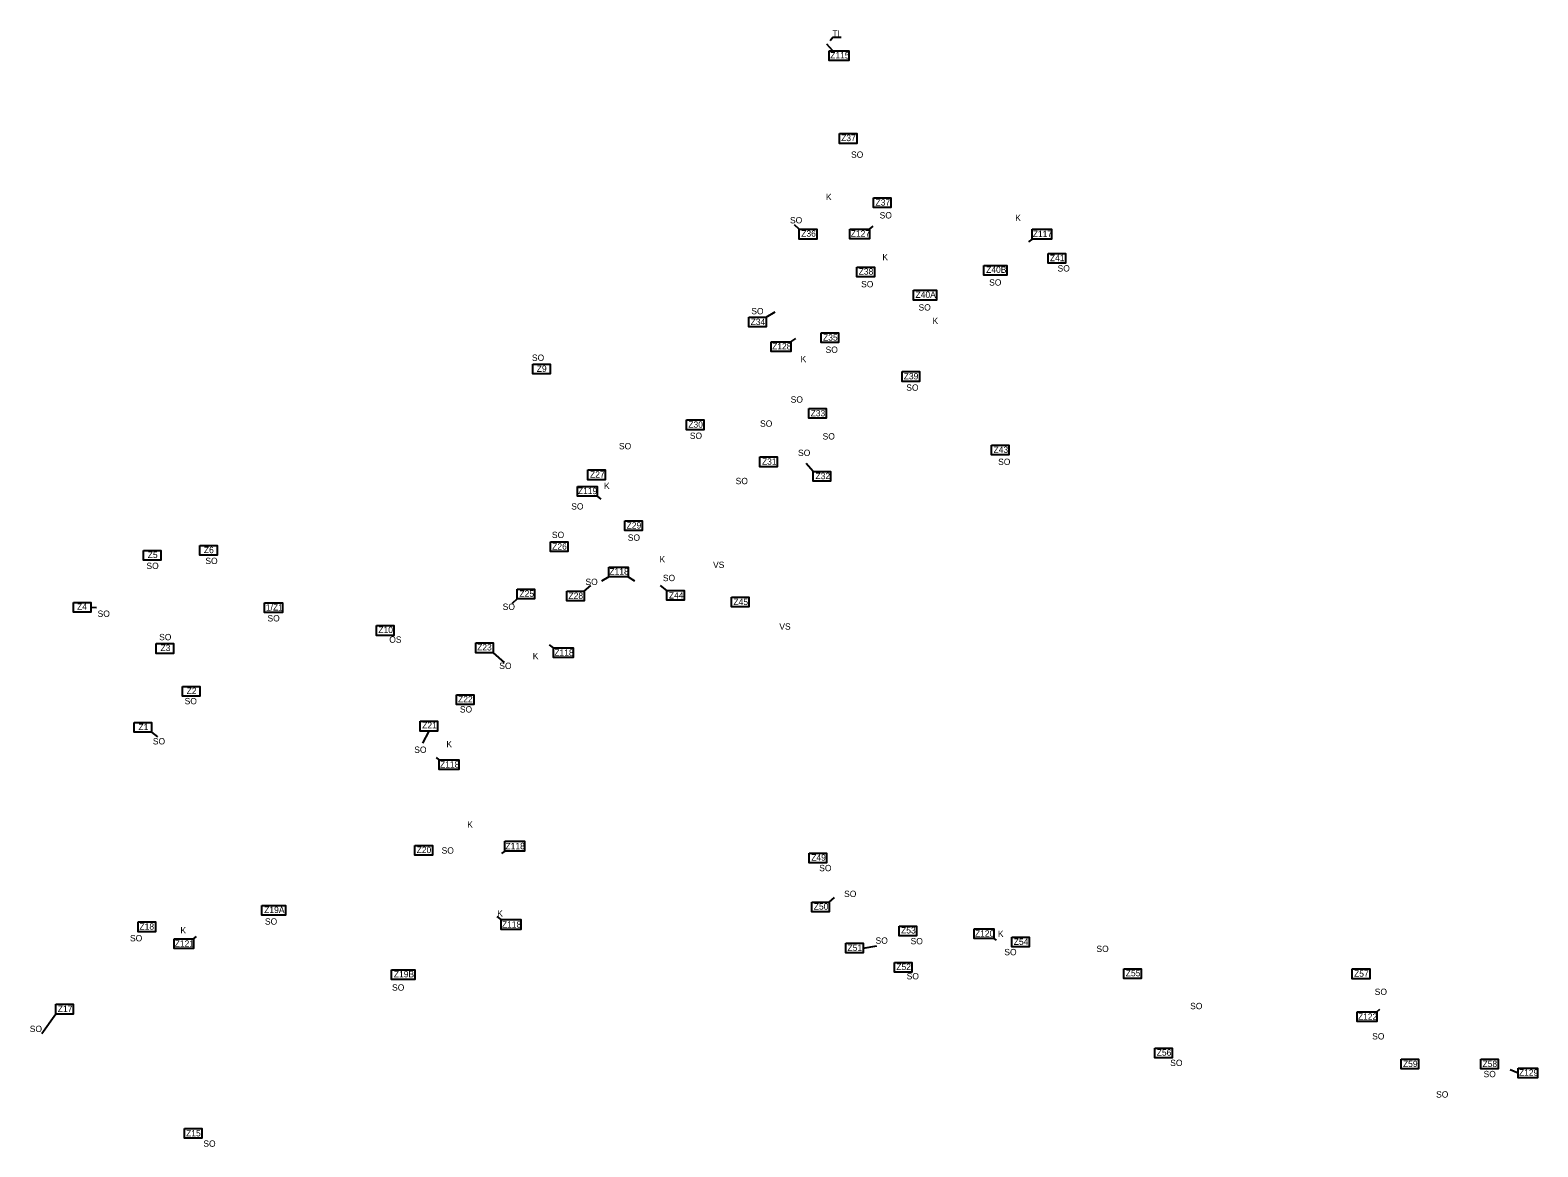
# Model space of a CAD drawing. Extents: x -443519 to -431242, y -1133468 to -1129615.
# Drawn here: x -443043 to -440666, y -1131535 to -1129775 of the extents above; entities that cross this region are included whole.
import ezdxf

# ---------------------------------------------------------------- set-up
doc = ezdxf.new("R2010")
doc.units = 0
for name, color, linetype in [('Vrstva 3', 7, 'Continuous'), ('Vrstva 4', 7, 'Continuous'), ('Vrstva 8', 7, 'Continuous')]:
    doc.layers.add(name, color=color, linetype=linetype)

msp = doc.modelspace()

# ---------------------------------------------------------------- linework, layer by layer
at = {"layer": 'Vrstva 3'}
for p, q in [((-441777.7, -1129807.7), (-441786.9, -1129797.4)), ((-441830.5, -1130088.9), (-441838, -1130081.7)), ((-441808.5, -1130470.4), (-441819.7, -1130457.7)), ((-442169.8, -1130659.1), (-442159.4, -1130650.4)), ((-442039.5, -1130658.1), (-442049.1, -1130650.3)), ((-442275.3, -1130671.3), (-442283.1, -1130678.3)), ((-442947.3, -1130684.5), (-442938.5, -1130684.6)), ((-442313.2, -1130756), (-442295.7, -1130771.4)), ((-442851.5, -1130881.4), (-442842.3, -1130888.4)), ((-442414.7, -1130879.5), (-442424.6, -1130898.5)), ((-441783.2, -1131148.9), (-441775.1, -1131141.9)), ((-441729.8, -1131221.4), (-441708.1, -1131217.9)), ((-443002.5, -1131325.5), (-443024.8, -1131356.8))]:
    msp.add_line(p, q, dxfattribs=at)
for points in [[(-441783.2, -1129807.7), (-441752.4, -1129807.7), (-441752.4, -1129823.1), (-441783.2, -1129823.1)], [(-441767.1, -1129938.1), (-441739.7, -1129938.1), (-441739.7, -1129953.5), (-441767.1, -1129953.5)], [(-441713.5, -1130039.3), (-441686.2, -1130039.3), (-441686.2, -1130054.7), (-441713.5, -1130054.7)], [(-441830.5, -1130088.9), (-441803.1, -1130088.9), (-441803.1, -1130104.3), (-441830.5, -1130104.3)], [(-441438.1, -1130126.8), (-441410.7, -1130126.8), (-441410.7, -1130142.2), (-441438.1, -1130142.2)], [(-441739.6, -1130148.5), (-441712.2, -1130148.5), (-441712.2, -1130163.9), (-441739.6, -1130163.9)], [(-441539.4, -1130145.7), (-441503.3, -1130145.7), (-441503.3, -1130161.1), (-441539.4, -1130161.1)], [(-441650.7, -1130185), (-441614.1, -1130185), (-441614.1, -1130200.4), (-441650.7, -1130200.4)], [(-441909.9, -1130227.3), (-441882.6, -1130227.3), (-441882.6, -1130242.7), (-441909.9, -1130242.7)], [(-441796.3, -1130252.1), (-441768.9, -1130252.1), (-441768.9, -1130267.5), (-441796.3, -1130267.5)], [(-442250.7, -1130301.4), (-442223.3, -1130301.4), (-442223.3, -1130316.8), (-442250.7, -1130316.8)], [(-441668.4, -1130313.2), (-441641, -1130313.2), (-441641, -1130328.6), (-441668.4, -1130328.6)], [(-441815.5, -1130371.3), (-441788.2, -1130371.3), (-441788.2, -1130386.7), (-441815.5, -1130386.7)], [(-442008.5, -1130389.3), (-441981.2, -1130389.3), (-441981.2, -1130404.7), (-442008.5, -1130404.7)], [(-441527.5, -1130428.9), (-441500.2, -1130428.9), (-441500.2, -1130444.3), (-441527.5, -1130444.3)], [(-441893, -1130447.6), (-441865.6, -1130447.6), (-441865.6, -1130463), (-441893, -1130463)], [(-442163.9, -1130468.1), (-442136.5, -1130468.1), (-442136.5, -1130483.5), (-442163.9, -1130483.5)], [(-441808.5, -1130470.4), (-441781.1, -1130470.4), (-441781.1, -1130485.8), (-441808.5, -1130485.8)], [(-442105.4, -1130548.2), (-442078, -1130548.2), (-442078, -1130563.6), (-442105.4, -1130563.6)], [(-442222.8, -1130581.2), (-442195.5, -1130581.2), (-442195.5, -1130596.5), (-442222.8, -1130596.5)], [(-442864.1, -1130595.1), (-442836.8, -1130595.1), (-442836.8, -1130610.4), (-442864.1, -1130610.4)], [(-442775.7, -1130587.1), (-442748.3, -1130587.1), (-442748.3, -1130602.5), (-442775.7, -1130602.5)], [(-442275.3, -1130655.9), (-442247.9, -1130655.9), (-442247.9, -1130671.3), (-442275.3, -1130671.3)], [(-442039.5, -1130658.1), (-442012.1, -1130658.1), (-442012.1, -1130673.5), (-442039.5, -1130673.5)], [(-442974.7, -1130676.8), (-442947.3, -1130676.8), (-442947.3, -1130692.2), (-442974.7, -1130692.2)], [(-442673.7, -1130677.5), (-442645, -1130677.5), (-442645, -1130692.9), (-442673.7, -1130692.9)], [(-442197.1, -1130659.1), (-442169.8, -1130659.1), (-442169.8, -1130674.5), (-442197.1, -1130674.5)], [(-441937.3, -1130668.5), (-441909.9, -1130668.5), (-441909.9, -1130683.9), (-441937.3, -1130683.9)], [(-442497.1, -1130713.3), (-442469.7, -1130713.3), (-442469.7, -1130728.7), (-442497.1, -1130728.7)], [(-442844.2, -1130741.8), (-442816.9, -1130741.8), (-442816.9, -1130757.2), (-442844.2, -1130757.2)], [(-442340.6, -1130740.6), (-442313.2, -1130740.6), (-442313.2, -1130756), (-442340.6, -1130756)], [(-442802.8, -1130809.3), (-442775.4, -1130809.3), (-442775.4, -1130824.7), (-442802.8, -1130824.7)], [(-442370.9, -1130822.5), (-442343.6, -1130822.5), (-442343.6, -1130837.9), (-442370.9, -1130837.9)], [(-442878.9, -1130866.1), (-442851.5, -1130866.1), (-442851.5, -1130881.4), (-442878.9, -1130881.4)], [(-442428.4, -1130864.1), (-442401, -1130864.1), (-442401, -1130879.5), (-442428.4, -1130879.5)], [(-442436.4, -1131059.8), (-442409, -1131059.8), (-442409, -1131075.2), (-442436.4, -1131075.2)], [(-441815, -1131072), (-441787.6, -1131072), (-441787.6, -1131087.4), (-441815, -1131087.4)], [(-442677.7, -1131154.3), (-442640.5, -1131154.3), (-442640.5, -1131169.7), (-442677.7, -1131169.7)], [(-441810.6, -1131148.9), (-441783.2, -1131148.9), (-441783.2, -1131164.3), (-441810.6, -1131164.3)], [(-442872.7, -1131180.4), (-442845.3, -1131180.4), (-442845.3, -1131195.7), (-442872.7, -1131195.7)], [(-441673.2, -1131186.9), (-441645.8, -1131186.9), (-441645.8, -1131202.2), (-441673.2, -1131202.2)], [(-441495.6, -1131204.2), (-441468.2, -1131204.2), (-441468.2, -1131219.6), (-441495.6, -1131219.6)], [(-441757.2, -1131213.7), (-441729.8, -1131213.7), (-441729.8, -1131229.1), (-441757.2, -1131229.1)], [(-441680.5, -1131244), (-441653.2, -1131244), (-441653.2, -1131259.4), (-441680.5, -1131259.4)], [(-442473.2, -1131255.7), (-442436.5, -1131255.7), (-442436.5, -1131271.1), (-442473.2, -1131271.1)], [(-441319, -1131254), (-441291.6, -1131254), (-441291.6, -1131269.4), (-441319, -1131269.4)], [(-440958.8, -1131254.3), (-440931.4, -1131254.3), (-440931.4, -1131269.7), (-440958.8, -1131269.7)], [(-443002.5, -1131310.1), (-442975.2, -1131310.1), (-442975.2, -1131325.5), (-443002.5, -1131325.5)], [(-441270.2, -1131379), (-441242.8, -1131379), (-441242.8, -1131394.4), (-441270.2, -1131394.4)], [(-440882, -1131396.5), (-440854.6, -1131396.5), (-440854.6, -1131411.9), (-440882, -1131411.9)], [(-440756.3, -1131396.5), (-440728.9, -1131396.5), (-440728.9, -1131411.9), (-440756.3, -1131411.9)], [(-442799.7, -1131505.6), (-442772.3, -1131505.6), (-442772.3, -1131521), (-442799.7, -1131521)]]:
    msp.add_lwpolyline(points, close=True, dxfattribs=at)
at = {"layer": 'Vrstva 4'}
msp.add_lwpolyline([(-441764.3, -1129786.7), (-441777.7, -1129786.7), (-441781.9, -1129791.9)], dxfattribs=at)
at = {"layer": 'Vrstva 8'}
for p, q in [((-441720.1, -1130088.6), (-441714.3, -1130084)), ((-441463.6, -1130104.2), (-441469.4, -1130108.5)), ((-441882.6, -1130227.3), (-441868.4, -1130219.1)), ((-441844, -1130266.2), (-441836.1, -1130260.9)), ((-442149.3, -1130509.6), (-442143.6, -1130514.2)), ((-442131, -1130636.5), (-442142.2, -1130643.1)), ((-442100.3, -1130636.5), (-442090.5, -1130642.7)), ((-442217.8, -1130748.4), (-442224.2, -1130743.6)), ((-442398, -1130924.7), (-442402.3, -1130921.1)), ((-442294.8, -1131068.6), (-442299.8, -1131072.4)), ((-442300.3, -1131176.7), (-442306.7, -1131171.9)), ((-442785.3, -1131206.9), (-442780.8, -1131203.4)), ((-441523.9, -1131206.4), (-441520.2, -1131209.2)), ((-440920.2, -1131322), (-440915.5, -1131317.9)), ((-440697.5, -1131418.4), (-440709.9, -1131413.3))]:
    msp.add_line(p, q, dxfattribs=at)
for points in [[(-441750.9, -1130088.6), (-441720.1, -1130088.6), (-441720.1, -1130104), (-441750.9, -1130104)], [(-441463.6, -1130088.8), (-441432.8, -1130088.8), (-441432.8, -1130104.2), (-441463.6, -1130104.2)], [(-441463.6, -1130088.8), (-441432.8, -1130088.8), (-441432.8, -1130104.2), (-441463.6, -1130104.2)], [(-441874.8, -1130266.2), (-441844, -1130266.2), (-441844, -1130281.6), (-441874.8, -1130281.6)], [(-442180.1, -1130494.2), (-442149.3, -1130494.2), (-442149.3, -1130509.6), (-442180.1, -1130509.6)], [(-442131, -1130621.1), (-442100.3, -1130621.1), (-442100.3, -1130636.5), (-442131, -1130636.5)], [(-442217.8, -1130748.4), (-442187, -1130748.4), (-442187, -1130763.8), (-442217.8, -1130763.8)], [(-442398, -1130924.7), (-442367.2, -1130924.7), (-442367.2, -1130940.1), (-442398, -1130940.1)], [(-442294.8, -1131053.2), (-442264, -1131053.2), (-442264, -1131068.6), (-442294.8, -1131068.6)], [(-442300.3, -1131176.7), (-442269.5, -1131176.7), (-442269.5, -1131192.1), (-442300.3, -1131192.1)], [(-441554.7, -1131191), (-441523.9, -1131191), (-441523.9, -1131206.4), (-441554.7, -1131206.4)], [(-442816.1, -1131206.9), (-442785.3, -1131206.9), (-442785.3, -1131222.3), (-442816.1, -1131222.3)], [(-440951, -1131322), (-440920.2, -1131322), (-440920.2, -1131337.4), (-440951, -1131337.4)], [(-440697.5, -1131410.7), (-440666.8, -1131410.7), (-440666.8, -1131426.1), (-440697.5, -1131426.1)]]:
    msp.add_lwpolyline(points, close=True, dxfattribs=at)

# ---------------------------------------------------------------- texts
at = {"layer": 'Vrstva 3'}
for s, p in [('Z115', (-441781.8, -1129819.7)), ('Z37', (-441764.6, -1129949.9)), ('Z37', (-441710.4, -1130051.5)), ('Z36', (-441827.5, -1130100.6)), ('Z41', (-441435.5, -1130139.1)), ('Z38', (-441736.9, -1130160.4)), ('Z40B', (-441536, -1130157.5)), ('Z40A', (-441647.3, -1130196.9)), ('Z34', (-441907.3, -1130239.7)), ('Z35', (-441793.1, -1130264.3)), ('Z9', (-442244.4, -1130313.5)), ('Z39', (-441665.9, -1130325.4)), ('Z30', (-442005.5, -1130401.6)), ('Z33', (-441812.7, -1130383.7)), ('Z43', (-441524.3, -1130441.2)), ('Z31', (-441889.4, -1130459.9)), ('Z27', (-442160.4, -1130480.1)), ('Z32', (-441805, -1130482.6)), ('Z29', (-442102.7, -1130560.4)), ('Z26', (-442220.1, -1130593.6)), ('Z5', (-442857.7, -1130606.9)), ('Z6', (-442769.2, -1130599.2)), ('Z25', (-442271.7, -1130668)), ('Z4', (-442969.1, -1130688.5)), ('1/Z1', (-442671.4, -1130689.6)), ('Z28', (-442194.4, -1130671.3)), ('Z44', (-442036.1, -1130670.7)), ('Z45', (-441934.4, -1130681)), ('Z10', (-442494.1, -1130725)), ('Z3', (-442837.5, -1130753.5)), ('Z23', (-442338.4, -1130752.5)), ('Z2', (-442796.3, -1130821.1)), ('Z22', (-442368.4, -1130834.2)), ('Z1', (-442872.3, -1130878.1)), ('Z21', (-442425, -1130875.4)), ('Z20', (-442433.8, -1131071.9)), ('Z49', (-441811.7, -1131083.8)), ('Z19A', (-442674.1, -1131166.3)), ('Z50', (-441807.7, -1131160.9)), ('Z18', (-442870.7, -1131192.5)), ('Z53', (-441670.1, -1131198.5)), ('Z51', (-441754.6, -1131226.1)), ('Z54', (-441492.5, -1131216.4)), ('Z52', (-441677.6, -1131256)), ('Z19B', (-442469.7, -1131267.7)), ('Z55', (-441315.9, -1131266)), ('Z57', (-440956, -1131266.7)), ('Z17', (-442999.4, -1131322.1)), ('Z56', (-441267.1, -1131391.1)), ('Z59', (-440878.9, -1131409)), ('Z58', (-440753.5, -1131409)), ('Z15', (-442797.2, -1131518.3))]:
    msp.add_text(s, height=10, dxfattribs=at).set_placement(p)
at = {"layer": 'Vrstva 4'}
for s, p in [('TI', (-441778.4, -1129785.1)), ('SO', (-441749, -1129976.2)), ('K', (-441788.5, -1130042.9)), ('SO', (-441703.9, -1130071.8)), ('SO', (-441845.2, -1130079.6)), ('K', (-441490.1, -1130075.8)), ('K', (-441699.6, -1130137.8)), ('SO', (-441423.4, -1130155.4)), ('SO', (-441733.1, -1130180.3)), ('SO', (-441531.3, -1130177.6)), ('SO', (-441906.2, -1130222.8)), ('SO', (-441642.6, -1130216.9)), ('K', (-441620.6, -1130238.2)), ('SO', (-441789.1, -1130283.6)), ('SO', (-442252, -1130296.2)), ('K', (-441828.5, -1130298.3)), ('SO', (-441661.9, -1130343.3)), ('SO', (-441844.1, -1130362.1)), ('SO', (-441892.4, -1130400)), ('SO', (-442003.1, -1130419.2)), ('SO', (-441793.8, -1130420.1)), ('SO', (-442114.8, -1130435.6)), ('SO', (-441832.5, -1130446.1)), ('SO', (-441517.1, -1130460.2)), ('K', (-442138.4, -1130498.1)), ('SO', (-441930.9, -1130490.5)), ('SO', (-442190.1, -1130530.5)), ('SO', (-442220.5, -1130575.4)), ('SO', (-442100.9, -1130579.7)), ('SO', (-442766.8, -1130616.4)), ('K', (-442050.9, -1130613.8)), ('SO', (-442859.7, -1130624.2)), ('SO', (-442045.6, -1130643.3)), ('VS', (-441966.5, -1130622.5)), ('SO', (-442167.6, -1130649.4)), ('SO', (-442298.1, -1130688.6)), ('SO', (-442936.7, -1130699.6)), ('SO', (-442668.9, -1130706.8)), ('SO', (-442839.7, -1130736.4)), ('VS', (-441862, -1130719.8)), ('OS', (-442476.9, -1130740.4)), ('SO', (-442303.5, -1130781.7)), ('K', (-442250.7, -1130766.3)), ('SO', (-442799.5, -1130837.3)), ('SO', (-442365.6, -1130850.3)), ('SO', (-442849.6, -1130900.6)), ('K', (-442386.9, -1130905.2)), ('SO', (-442437.5, -1130913.9)), ('K', (-442354, -1131031.8)), ('SO', (-442394.4, -1131072.7)), ('SO', (-441799.1, -1131100.4)), ('SO', (-441759.9, -1131141.1)), ('SO', (-442672.9, -1131184.6)), ('K', (-442306.7, -1131171.9)), ('SO', (-442885.6, -1131210.9)), ('K', (-442806.1, -1131198.5)), ('SO', (-441710.3, -1131214.7)), ('K', (-441517.4, -1131204)), ('SO', (-441655.1, -1131215.5)), ('SO', (-441507.3, -1131232.8)), ('SO', (-441362.1, -1131227.7)), ('SO', (-441661.3, -1131270.8)), ('SO', (-442472.5, -1131288.6)), ('SO', (-440923.4, -1131295.4)), ('SO', (-441214.4, -1131317.8)), ('SO', (-443043.6, -1131353.8)), ('SO', (-440927.5, -1131365.5)), ('SO', (-441245.8, -1131407.4)), ('SO', (-440751.9, -1131425)), ('SO', (-440826.7, -1131457.1)), ('SO', (-442770, -1131534.6))]:
    msp.add_text(s, height=10, dxfattribs=at).set_placement(p)
at = {"layer": 'Vrstva 8'}
for s, p in [('Z127', (-441749.5, -1130100.6)), ('Z117', (-441462.5, -1130101.2)), ('Z128', (-441873.4, -1130278.2)), ('Z119', (-442179.6, -1130506.2)), ('Z118', (-442129.9, -1130632.9)), ('Z118', (-442216.7, -1130760.9)), ('Z118', (-442396.9, -1130937.1)), ('Z118', (-442293.7, -1131065.7)), ('Z118', (-442299.3, -1131189.2)), ('Z120', (-441553.6, -1131203.5)), ('Z121', (-442815.1, -1131219.3)), ('Z122', (-440949.9, -1131334.5)), ('Z129', (-440696.1, -1131422.7))]:
    msp.add_text(s, height=10, dxfattribs=at).set_placement(p)

doc.saveas('drawing.dxf')
